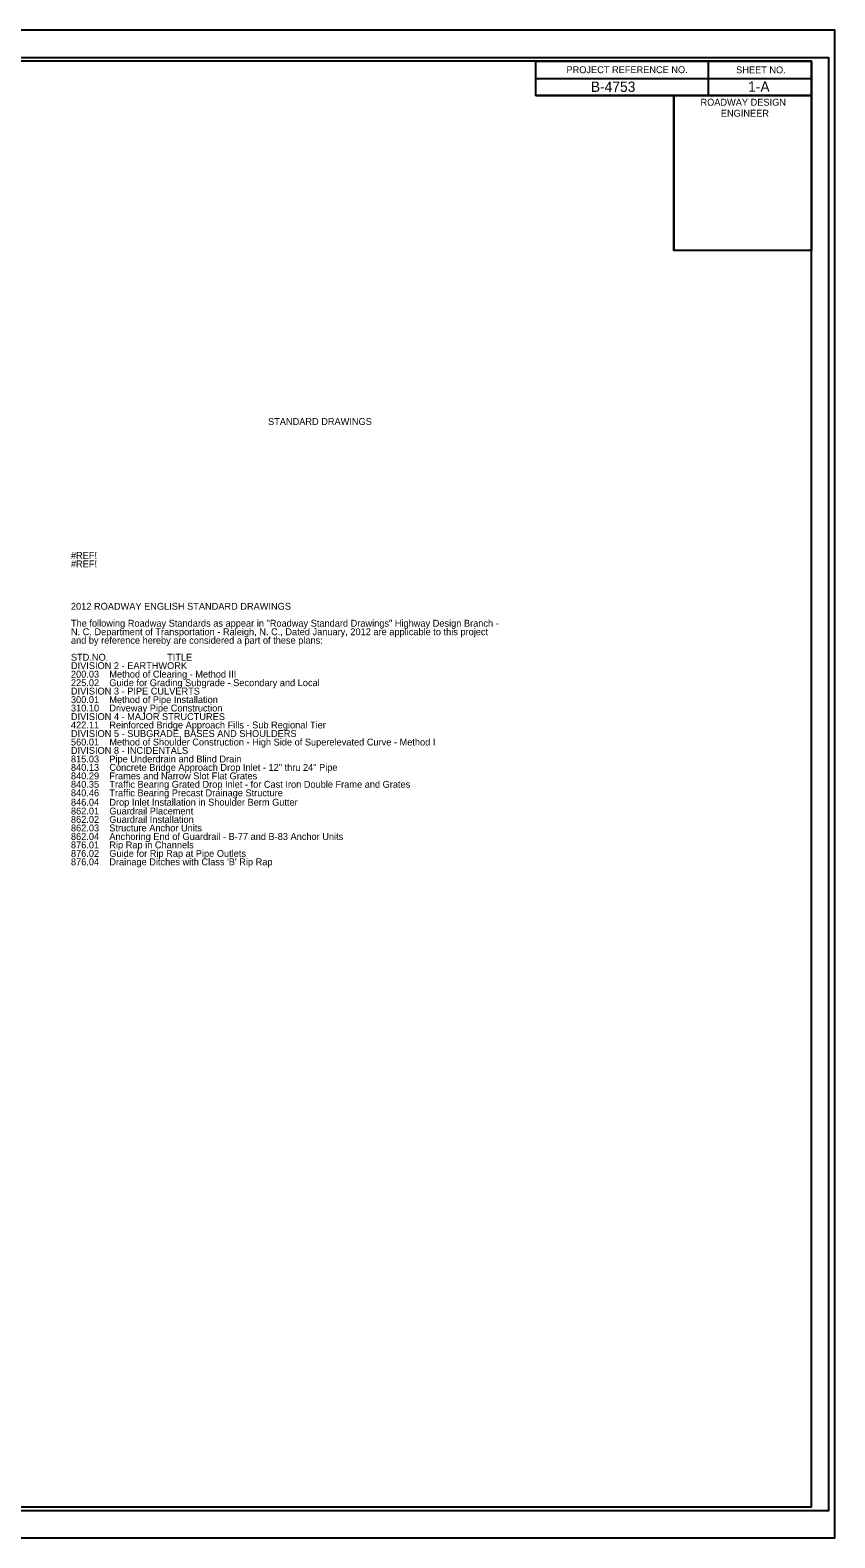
# Model space of a CAD drawing. Extents: x 573855 to 575539, y -53293 to -50956.
# Drawn here: x 574955 to 575539, y -52051 to -50956 of the extents above; entities that cross this region are included whole.
import ezdxf

# ---------------------------------------------------------------- set-up
doc = ezdxf.new("R2010")
doc.units = 0
for name, color, linetype in [('Default', 7, 'Continuous'), ('Sheet Cutting Line CELL', 7, 'Continuous'), ('Sheet Data Field CELL', 7, 'Continuous'), ('Sheet Plan CELL', 7, 'Continuous'), ('Sheet Plot Border Inside CELL', 7, 'Continuous'), ('Sheet Plot Border Outside CELL', 7, 'Continuous'), ('Sheet Summary CELL', 7, 'Continuous')]:
    doc.layers.add(name, color=color, linetype=linetype)

msp = doc.modelspace()

# ---------------------------------------------------------------- linework, layer by layer
at = {"layer": 'Sheet Cutting Line CELL'}
for p, q in [((575539.2, -50955.8), (573855.7, -50955.8)), ((573855.7, -52050.8), (575539.2, -52050.8))]:
    msp.add_line(p, q, dxfattribs=at)
at = {"layer": 'Sheet Plan CELL'}
for p, q in [((575447.2, -50978.3), (575447.2, -51003.3)), ((575322.1, -50990.8), (575522.2, -50990.8)), ((575322.1, -51003.3), (575522.2, -51003.3)), ((575322.1, -51003.3), (575522.2, -51003.3)), ((575422.2, -51003.3), (575422.2, -51115.8))]:
    msp.add_line(p, q, dxfattribs=at)
for points in [[(575522.2, -50978.3), (574022.2, -50978.3), (574022.2, -52028.3), (575522.2, -52028.3)], [(575322.1, -50978.3), (575522.2, -50978.3), (575522.2, -51003.3), (575322.1, -51003.3)], [(575422.2, -51003.3), (575522.2, -51003.3), (575522.2, -51115.8), (575422.2, -51115.8)]]:
    msp.add_lwpolyline(points, close=True, dxfattribs=at)
at = {"layer": 'Sheet Plot Border Inside CELL'}
msp.add_lwpolyline([(573868.7, -52030.8), (575534.7, -52030.8), (575534.7, -50975.8), (573868.7, -50975.8)], close=True, dxfattribs=at)
at = {"layer": 'Sheet Plot Border Outside CELL'}
msp.add_lwpolyline([(573855.7, -52050.8), (575539.2, -52050.8), (575539.2, -50955.8), (573855.7, -50955.8)], close=True, dxfattribs=at)

# ---------------------------------------------------------------- texts
at = {"layer": 'Default'}
for s, p in [('#REF!', (574984.5, -51339.8)), ('#REF!', (574984.5, -51345.9)), ('2012 ROADWAY ENGLISH STANDARD DRAWINGS', (574984.5, -51376.7)), ('The following Roadway Standards as appear in "Roadway Standard Drawings" Highway Design Branch -', (574984.5, -51389)), ('and by reference hereby are considered a part of these plans:', (574984.5, -51401.4)), ('N. C. Department of Transportation - Raleigh, N. C., Dated January, 2012 are applicable to this project', (574984.5, -51395.2)), ('STD.NO.                       TITLE', (574984.5, -51413.7)), ('200.03    Method of Clearing - Method III', (574984.5, -51426)), ('DIVISION 2 - EARTHWORK', (574984.5, -51419.8)), ('225.02    Guide for Grading Subgrade - Secondary and Local', (574984.5, -51432.2)), ('300.01    Method of Pipe Installation ', (574984.5, -51444.5)), ('DIVISION 3 - PIPE CULVERTS', (574984.5, -51438.3)), ('310.10    Driveway Pipe Construction', (574984.5, -51450.6)), ('DIVISION 4 - MAJOR STRUCTURES', (574984.5, -51456.8)), ('422.11    Reinforced Bridge Approach Fills - Sub Regional Tier', (574984.5, -51462.9)), ('DIVISION 5 - SUBGRADE, BASES AND SHOULDERS', (574984.5, -51469.1)), ('560.01    Method of Shoulder Construction - High Side of Superelevated Curve - Method I', (574984.5, -51475.3)), ('815.03    Pipe Underdrain and Blind Drain', (574984.5, -51487.6)), ('DIVISION 8 - INCIDENTALS', (574984.5, -51481.4)), ('840.13    Concrete Bridge Approach Drop Inlet - 12" thru 24" Pipe ', (574984.5, -51493.7)), ('840.29    Frames and Narrow Slot Flat Grates', (574984.5, -51499.9)), ('840.35    Traffic Bearing Grated Drop Inlet - for Cast Iron Double Frame and Grates', (574984.5, -51506)), ('840.46    Traffic Bearing Precast Drainage Structure', (574984.5, -51512.2)), ('846.04    Drop Inlet Installation in Shoulder Berm Gutter', (574984.5, -51519)), ('862.01    Guardrail Placement', (574984.5, -51525.4)), ('862.02    Guardrail Installation', (574984.5, -51531.5)), ('862.03    Structure Anchor Units', (574984.5, -51537.7)), ('862.04    Anchoring End of Guardrail - B-77 and B-83 Anchor Units', (574984.5, -51543.9)), ('876.01    Rip Rap in Channels', (574984.5, -51550)), ('876.02    Guide for Rip Rap at Pipe Outlets', (574984.5, -51556.2)), ("876.04    Drainage Ditches with Class 'B' Rip Rap", (574984.5, -51562.3))]:
    msp.add_text(s, height=5, dxfattribs=at).set_placement(p)
at = {"layer": 'Sheet Data Field CELL'}
for s, p in [('B-4753  ', (575362, -51000.6)), ('1-A', (575476.2, -51000.5))]:
    msp.add_text(s, height=7.5, rotation=360, dxfattribs=at).set_placement(p)
at = {"layer": 'Sheet Plan CELL'}
for s, p in [('PROJECT REFERENCE NO.', (575344.3, -50987)), ('SHEET NO.', (575467.5, -50987.1)), ('ROADWAY DESIGN', (575441.6, -51010.6)), ('ENGINEER', (575456.4, -51018.6))]:
    msp.add_text(s, height=5, rotation=360, dxfattribs=at).set_placement(p)
at = {"layer": 'Sheet Summary CELL'}
msp.add_text('STANDARD DRAWINGS', height=5, rotation=360, dxfattribs=at).set_placement((575127.6, -51242.5))

doc.saveas('drawing.dxf')
